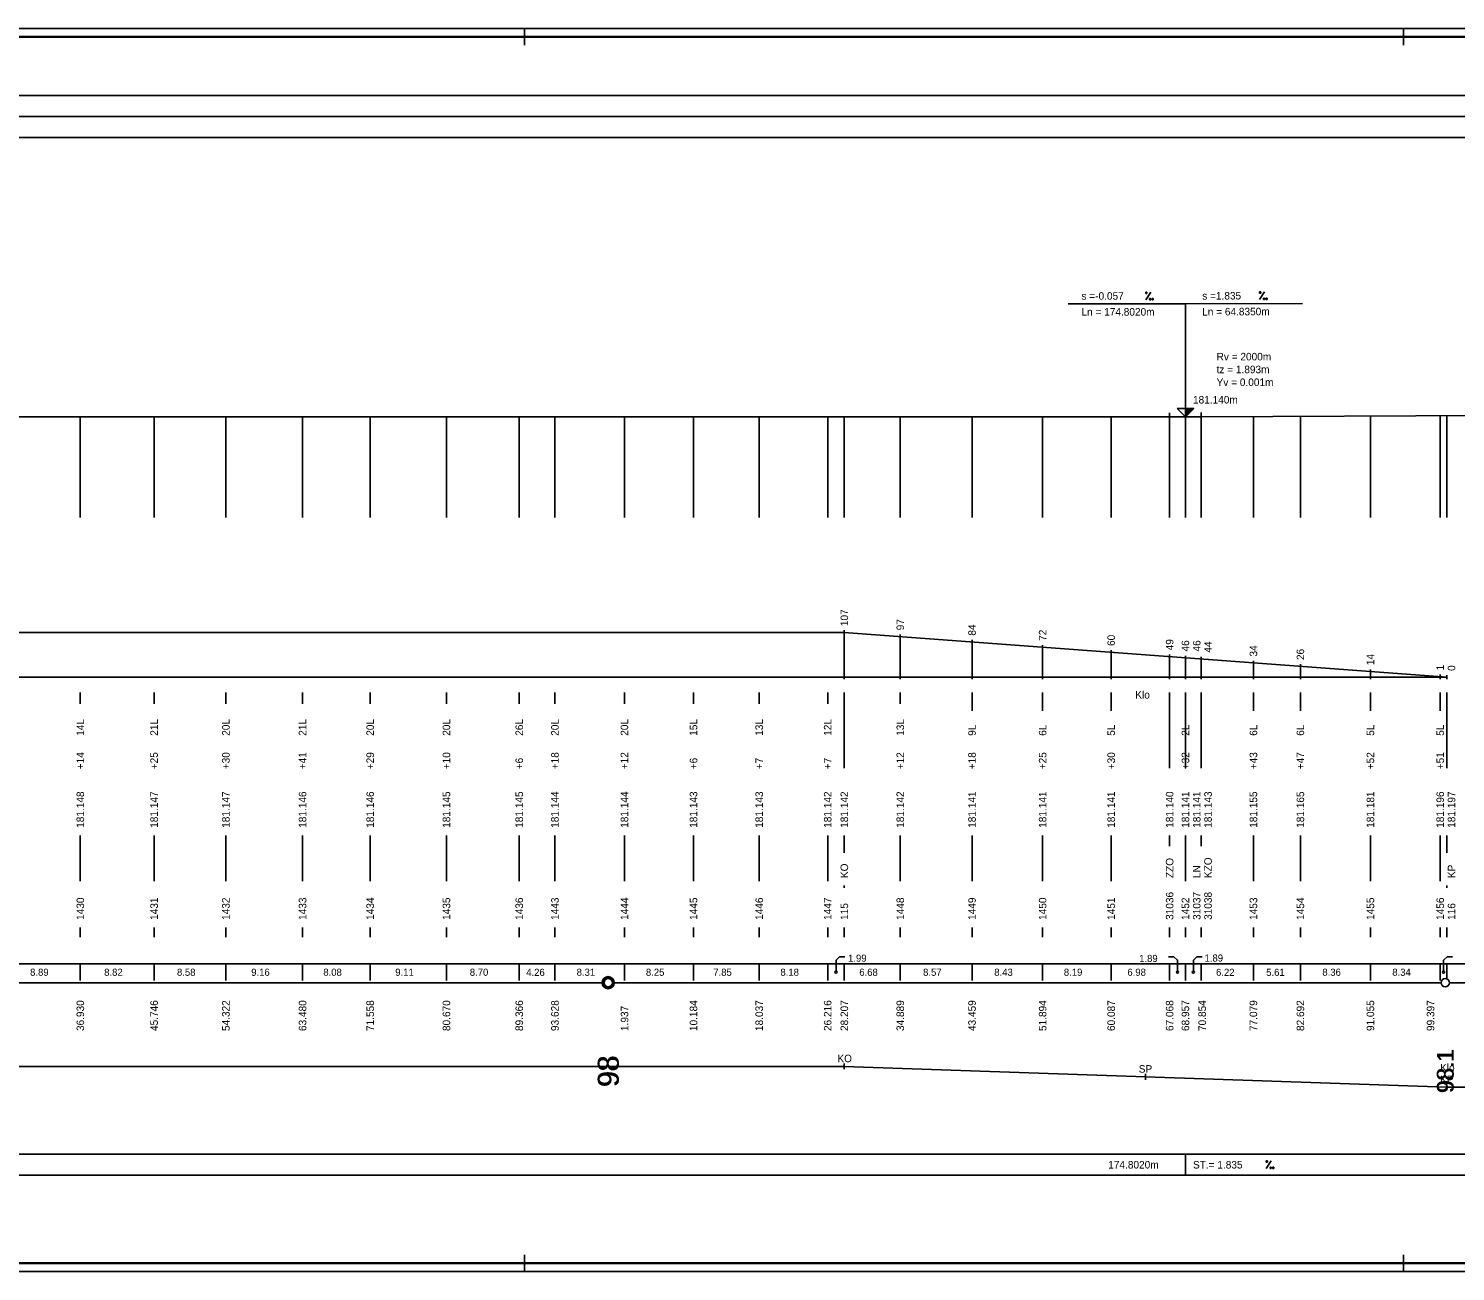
# Model space of a CAD drawing. Extents: x 0 to 10087, y -805 to 297.
# Drawn here: x 3241.5 to 3582.4, y 0 to 297 of the extents above; entities that cross this region are included whole.
import ezdxf

# ---------------------------------------------------------------- set-up
doc = ezdxf.new("R2010")
doc.units = 0
for name, color, linetype in [('CARKY_HODNOT', 7, 'Continuous'), ('KRIV1_CARA', 7, 'Continuous'), ('KRIV1_TEXT', 7, 'Continuous'), ('NIVELETA_CARA', 7, 'Continuous'), ('NIVELETA_TEXT', 7, 'Continuous'), ('PREV_CARA', 7, 'Continuous'), ('PREV_TEXT', 7, 'Continuous'), ('RAM', 7, 'Continuous'), ('REZERVA', 7, 'Continuous'), ('STAN_CARA', 7, 'Continuous'), ('STAN_PAS', 7, 'Continuous'), ('STAN_TEXT', 7, 'Continuous'), ('TEXT', 7, 'Continuous'), ('TXT_C_BODU', 7, 'Continuous')]:
    doc.layers.add(name, color=color, linetype=linetype)

msp = doc.modelspace()

# ---------------------------------------------------------------- linework, layer by layer
at = {"layer": 'CARKY_HODNOT'}
for p, q in [((3253.86, 180.14), (3253.86, 204.24)), ((3271.49, 180.14), (3271.49, 204.24)), ((3288.64, 180.14), (3288.64, 204.23)), ((3306.96, 180.14), (3306.96, 204.23)), ((3323.12, 180.14), (3323.12, 204.23)), ((3341.34, 180.14), (3341.34, 204.23)), ((3358.73, 180.14), (3358.73, 204.22)), ((3367.26, 180.14), (3367.26, 204.22)), ((3383.87, 180.14), (3383.87, 204.22)), ((3400.37, 180.14), (3400.37, 204.22)), ((3416.07, 180.14), (3416.07, 204.21)), ((3432.43, 180.14), (3432.43, 204.21)), ((3436.41, 180.14), (3436.41, 204.21)), ((3449.78, 180.14), (3449.78, 204.21)), ((3466.92, 180.14), (3466.92, 204.21)), ((3483.79, 180.14), (3483.79, 204.2)), ((3500.17, 180.14), (3500.17, 204.2)), ((3514.14, 180.14), (3514.14, 204.2)), ((3517.91, 180.14), (3517.91, 204.2)), ((3517.92, 180.14), (3517.92, 204.2)), ((3521.71, 180.14), (3521.71, 204.22)), ((3534.16, 180.14), (3534.16, 204.27)), ((3545.38, 180.14), (3545.38, 204.33)), ((3562.11, 180.14), (3562.11, 204.4)), ((3578.79, 180.14), (3578.79, 204.48)), ((3580.41, 180.14), (3580.41, 204.49)), ((3253.86, 135.65), (3253.86, 138.35)), ((3271.49, 135.65), (3271.49, 138.35)), ((3288.64, 135.65), (3288.64, 138.35)), ((3306.96, 135.65), (3306.96, 138.35)), ((3323.12, 135.65), (3323.12, 138.35)), ((3341.34, 135.65), (3341.34, 138.35)), ((3358.73, 135.65), (3358.73, 138.35)), ((3367.26, 135.65), (3367.26, 138.35)), ((3383.87, 135.65), (3383.87, 138.35)), ((3400.37, 135.65), (3400.37, 138.35)), ((3416.07, 135.65), (3416.07, 138.35)), ((3432.43, 135.65), (3432.43, 138.35)), ((3436.41, 126.2), (3436.41, 138.35)), ((3449.78, 135.65), (3449.78, 138.35)), ((3466.92, 134), (3466.92, 138.35)), ((3483.79, 134), (3483.79, 138.35)), ((3500.17, 134), (3500.17, 138.35)), ((3514.14, 126.2), (3514.14, 138.35)), ((3517.91, 134), (3517.91, 138.35)), ((3517.92, 126.2), (3517.92, 138.35)), ((3521.71, 126.2), (3521.71, 138.35)), ((3534.16, 134), (3534.16, 138.35)), ((3545.38, 134), (3545.38, 138.35)), ((3562.11, 134), (3562.11, 138.35)), ((3578.79, 134), (3578.79, 138.35)), ((3580.41, 126.2), (3580.41, 138.35)), ((3436.41, 120.25), (3436.41, 126.2)), ((3514.14, 120.25), (3514.14, 126.2)), ((3517.92, 120.25), (3517.92, 126.2)), ((3521.71, 120.25), (3521.71, 126.2)), ((3580.41, 120.25), (3580.41, 126.2)), ((3253.86, 93.3), (3253.86, 104.2)), ((3271.49, 93.3), (3271.49, 104.2)), ((3288.64, 93.3), (3288.64, 104.2)), ((3306.96, 93.3), (3306.96, 104.2)), ((3323.12, 93.3), (3323.12, 104.2)), ((3341.34, 93.3), (3341.34, 104.2)), ((3358.73, 93.3), (3358.73, 104.2)), ((3367.26, 93.3), (3367.26, 104.2)), ((3383.87, 93.3), (3383.87, 104.2)), ((3400.37, 93.3), (3400.37, 104.2)), ((3416.07, 93.3), (3416.07, 104.2)), ((3432.43, 93.3), (3432.43, 104.2)), ((3436.41, 100), (3436.41, 104.2)), ((3449.78, 93.3), (3449.78, 104.2)), ((3466.92, 93.3), (3466.92, 104.2)), ((3483.79, 93.3), (3483.79, 104.2)), ((3500.17, 93.3), (3500.17, 104.2)), ((3514.14, 101.65), (3514.14, 104.2)), ((3517.91, 93.3), (3517.91, 104.2)), ((3517.92, 100), (3517.92, 104.2)), ((3521.71, 101.65), (3521.71, 104.2)), ((3534.16, 93.3), (3534.16, 104.2)), ((3545.38, 93.3), (3545.38, 104.2)), ((3562.11, 93.3), (3562.11, 104.2)), ((3578.79, 93.3), (3578.79, 104.2)), ((3580.41, 100), (3580.41, 104.2)), ((3436.41, 91.65), (3436.41, 92.2)), ((3580.41, 91.65), (3580.41, 92.2)), ((3253.86, 79.9), (3253.86, 82.2)), ((3271.49, 79.9), (3271.49, 82.2)), ((3288.64, 79.9), (3288.64, 82.2)), ((3306.96, 79.9), (3306.96, 82.2)), ((3323.12, 79.9), (3323.12, 82.2)), ((3341.34, 79.9), (3341.34, 82.2)), ((3358.73, 79.9), (3358.73, 82.2)), ((3367.26, 79.9), (3367.26, 82.2)), ((3383.87, 79.9), (3383.87, 82.2)), ((3400.37, 79.9), (3400.37, 82.2)), ((3416.07, 79.9), (3416.07, 82.2)), ((3432.43, 79.9), (3432.43, 82.2)), ((3436.41, 79.9), (3436.41, 82.2)), ((3449.78, 79.9), (3449.78, 82.2)), ((3466.92, 79.9), (3466.92, 82.2)), ((3483.79, 79.9), (3483.79, 82.2)), ((3500.17, 79.9), (3500.17, 82.2)), ((3514.14, 79.9), (3514.14, 82.2)), ((3517.91, 79.9), (3517.91, 82.2)), ((3517.92, 79.9), (3517.92, 82.2)), ((3521.71, 79.9), (3521.71, 82.2)), ((3534.16, 79.9), (3534.16, 82.2)), ((3545.38, 79.9), (3545.38, 82.2)), ((3562.11, 79.9), (3562.11, 82.2)), ((3578.79, 79.9), (3578.79, 82.2)), ((3580.41, 79.9), (3580.41, 82.2))]:
    msp.add_line(p, q, dxfattribs=at)
at = {"layer": 'KRIV1_CARA'}
for p, q in [((3011.07, 49), (3436.41, 49)), ((3436.41, 49), (3436.41, 49.7)), ((3436.41, 49), (3580.41, 44)), ((3436.41, 49), (3436.41, 48.3)), ((3508.41, 46.5), (3508.41, 47.2)), ((3508.41, 46.5), (3508.41, 45.8)), ((3580.41, 44), (3580.41, 44.7)), ((3580.41, 44), (3580.41, 43.3)), ((3580.41, 44), (4035.16, 44))]:
    msp.add_line(p, q, dxfattribs=at)
at = {"layer": 'NIVELETA_CARA'}
for p, q in [((300, 281), (8321.33, 281)), ((300, 276), (8321.33, 276)), ((300, 271), (8321.33, 271)), ((3517.92, 231.2), (3489.92, 231.2)), ((3517.92, 231.2), (3545.92, 231.33)), ((3517.92, 204.2), (3517.92, 231.2)), ((3514.14, 204.2), (3514.14, 205.2)), ((3517.92, 204.2), (3515.92, 206.2)), ((3515.92, 206.2), (3519.92, 206.2)), ((3517.92, 204.2), (3517.92, 206.2)), ((3519.92, 206.2), (3517.92, 204.2)), ((3517.99, 204.27), (3517.99, 206.2)), ((3518.06, 204.33), (3518.06, 206.2)), ((3518.12, 204.4), (3518.12, 206.2)), ((3518.19, 204.47), (3518.19, 206.2)), ((3518.26, 204.53), (3518.26, 206.2)), ((3518.32, 204.6), (3518.32, 206.2)), ((3518.39, 204.67), (3518.39, 206.2)), ((3518.46, 204.73), (3518.46, 206.2)), ((3518.52, 204.8), (3518.52, 206.2)), ((3518.59, 204.87), (3518.59, 206.2)), ((3518.66, 204.93), (3518.66, 206.2)), ((3518.72, 205), (3518.72, 206.2)), ((3518.79, 205.07), (3518.79, 206.2)), ((3518.86, 205.13), (3518.86, 206.2)), ((3518.92, 205.2), (3518.92, 206.2)), ((3518.99, 205.27), (3518.99, 206.2)), ((3519.06, 205.33), (3519.06, 206.2)), ((3519.12, 205.4), (3519.12, 206.2)), ((3519.19, 205.47), (3519.19, 206.2)), ((3519.26, 205.53), (3519.26, 206.2)), ((3519.32, 205.6), (3519.32, 206.2)), ((3519.39, 205.67), (3519.39, 206.2)), ((3519.46, 205.73), (3519.46, 206.2)), ((3519.52, 205.8), (3519.52, 206.2)), ((3519.59, 205.87), (3519.59, 206.2)), ((3519.66, 205.93), (3519.66, 206.2)), ((3519.72, 206), (3519.72, 206.2)), ((3519.79, 206.07), (3519.79, 206.2)), ((3519.86, 206.13), (3519.86, 206.2)), ((3519.92, 206.2), (3519.92, 206.2)), ((3521.71, 204.22), (3521.71, 205.22)), ((3521.71, 204.22), (3637.71, 204.75)), ((3175.58, 204.25), (3514.14, 204.2)), ((3514.14, 204.2), (3517.92, 204.2)), ((3514.14, 204.2), (3514.64, 204.2)), ((3514.64, 204.2), (3515.12, 204.2)), ((3517.92, 204.2), (3521.71, 204.22)), ((3520.72, 204.21), (3521.22, 204.22)), ((3521.22, 204.22), (3521.71, 204.22)), ((500, 28), (8321.33, 28)), ((3517.92, 23), (3517.92, 28)), ((500, 23), (8321.33, 23))]:
    msp.add_line(p, q, dxfattribs=at)
at = {"layer": 'NIVELETA_TEXT'}
for p, q in [((3508.42, 232.21), (3509.61, 234)), ((3508.42, 234), (3508.42, 233.7)), ((3508.43, 234), (3508.42, 233.99)), ((3508.42, 233.7), (3508.72, 233.7)), ((3508.72, 234), (3508.43, 234)), ((3508.72, 233.7), (3508.72, 234)), ((3509.33, 232.5), (3509.33, 232.2)), ((3509.34, 232.5), (3509.33, 232.49)), ((3509.33, 232.2), (3509.63, 232.2)), ((3509.63, 232.5), (3509.34, 232.5)), ((3509.63, 232.2), (3509.63, 232.5)), ((3509.95, 232.5), (3509.95, 232.2)), ((3510.24, 232.5), (3509.95, 232.5)), ((3509.95, 232.5), (3509.95, 232.49)), ((3509.95, 232.2), (3510.24, 232.2)), ((3510.24, 232.2), (3510.24, 232.5)), ((3535.62, 232.29), (3536.81, 234.08)), ((3535.62, 234.08), (3535.62, 233.78)), ((3535.91, 234.08), (3535.62, 234.08)), ((3535.62, 234.08), (3535.62, 234.07)), ((3535.62, 233.78), (3535.91, 233.78)), ((3535.91, 233.78), (3535.91, 234.08)), ((3536.53, 232.58), (3536.53, 232.29)), ((3536.54, 232.58), (3536.53, 232.58)), ((3536.53, 232.29), (3536.83, 232.29)), ((3536.83, 232.59), (3536.54, 232.58)), ((3536.83, 232.29), (3536.83, 232.59)), ((3537.15, 232.59), (3537.15, 232.29)), ((3537.44, 232.59), (3537.15, 232.59)), ((3537.15, 232.59), (3537.15, 232.58)), ((3537.15, 232.29), (3537.44, 232.29)), ((3537.44, 232.29), (3537.44, 232.59)), ((3537.22, 24.6), (3538.41, 26.4)), ((3537.22, 26.4), (3537.22, 26.1)), ((3537.23, 26.4), (3537.22, 26.39)), ((3537.22, 26.1), (3537.52, 26.1)), ((3537.52, 26.4), (3537.23, 26.4)), ((3537.52, 26.1), (3537.52, 26.4)), ((3538.13, 24.9), (3538.13, 24.6)), ((3538.14, 24.9), (3538.13, 24.89)), ((3538.13, 24.6), (3538.43, 24.6)), ((3538.43, 24.9), (3538.14, 24.9)), ((3538.43, 24.6), (3538.43, 24.9)), ((3538.75, 24.9), (3538.75, 24.6)), ((3539.04, 24.9), (3538.75, 24.9)), ((3538.75, 24.9), (3538.75, 24.89)), ((3538.75, 24.6), (3539.04, 24.6)), ((3539.04, 24.6), (3539.04, 24.9))]:
    msp.add_line(p, q, dxfattribs=at)
at = {"layer": 'PREV_CARA'}
for p, q in [((3011.07, 152.7), (3436.41, 152.7)), ((3580.41, 142), (3436.41, 152.7)), ((3011.07, 142), (3436.41, 142)), ((3580.41, 142), (3436.41, 142))]:
    msp.add_line(p, q, dxfattribs=at)
at = {"layer": 'PREV_TEXT'}
for p, q in [((3436.41, 141.5), (3436.41, 153.2)), ((3449.78, 141.5), (3449.78, 152.21)), ((3466.92, 141.5), (3466.92, 150.93)), ((3483.79, 141.5), (3483.79, 149.68)), ((3500.17, 141.5), (3500.17, 148.46)), ((3514.14, 141.5), (3514.14, 147.42)), ((3517.91, 141.5), (3517.91, 147.14)), ((3517.92, 141.5), (3517.92, 147.14)), ((3521.71, 141.5), (3521.71, 146.86)), ((3534.16, 141.5), (3534.16, 145.94)), ((3545.38, 141.5), (3545.38, 145.1)), ((3562.11, 141.5), (3562.11, 143.86)), ((3578.79, 141.5), (3578.79, 142.62)), ((3580.41, 141.5), (3580.41, 142.5))]:
    msp.add_line(p, q, dxfattribs=at)
at = {"layer": 'RAM'}
for p, q in [((8636.33, 297), (0, 297)), ((3360, 293), (3360, 297)), ((3570, 293), (3570, 297)), ((8634.33, 295.1), (2, 295.1)), ((8634.33, 295), (2, 295)), ((8634.33, 294.9), (2, 294.9)), ((3360, 0), (3360, 4)), ((3570, 0), (3570, 4)), ((0, 0), (8636.33, 0)), ((2, 2.1), (8634.33, 2.1)), ((2, 2), (8634.33, 2)), ((2, 1.9), (8634.33, 1.9))]:
    msp.add_line(p, q, dxfattribs=at)
at = {"layer": 'REZERVA'}
for centre, radius in [((3380, 69), 1.45), ((3380, 69), 1.4), ((3380, 69), 1.35), ((3380, 69), 1.3), ((3380, 69), 1.25), ((3380, 69), 1.2), ((3380, 69), 1.15), ((3380, 69), 1.1), ((3380, 69), 1.05), ((3380, 69), 1), ((3580, 69), 1)]:
    msp.add_circle(centre, radius, dxfattribs=at)
at = {"layer": 'STAN_CARA'}
for p, q in [((3181, 69), (3378.5, 69)), ((3381.5, 69), (3579, 69)), ((3581, 69), (3779, 69))]:
    msp.add_line(p, q, dxfattribs=at)
at = {"layer": 'STAN_PAS'}
for p, q in [((3434.42, 74.35), (3435.27, 75.2)), ((3435.27, 75.2), (3436.55, 75.2)), ((3515.18, 75.2), (3513.9, 75.2)), ((3516.03, 74.35), (3515.18, 75.2)), ((3519.81, 74.35), (3520.66, 75.2)), ((3520.66, 75.2), (3521.94, 75.2)), ((3579.6, 74.35), (3580.45, 75.2)), ((3580.45, 75.2), (3581.73, 75.2)), ((300, 73.5), (8321.33, 73.5)), ((3253.86, 69.5), (3253.86, 73.5)), ((3271.49, 69.5), (3271.49, 73.5)), ((3288.64, 69.5), (3288.64, 73.5)), ((3306.96, 69.5), (3306.96, 73.5)), ((3323.12, 69.5), (3323.12, 73.5)), ((3341.34, 69.5), (3341.34, 73.5)), ((3358.73, 69.5), (3358.73, 73.5)), ((3367.26, 69.5), (3367.26, 73.5)), ((3383.87, 69.5), (3383.87, 73.5)), ((3400.37, 69.5), (3400.37, 73.5)), ((3416.07, 69.5), (3416.07, 73.5)), ((3432.43, 69.5), (3432.43, 73.5)), ((3434.42, 71.75), (3434.42, 74.35)), ((3436.41, 69.5), (3436.41, 73.5)), ((3449.78, 69.5), (3449.78, 73.5)), ((3466.92, 69.5), (3466.92, 73.5)), ((3483.79, 69.5), (3483.79, 73.5)), ((3500.17, 69.5), (3500.17, 73.5)), ((3514.14, 69.5), (3514.14, 73.5)), ((3516.03, 71.75), (3516.03, 74.35)), ((3517.91, 69.5), (3517.91, 73.5)), ((3517.92, 69.5), (3517.92, 73.5)), ((3519.81, 71.75), (3519.81, 74.35)), ((3521.71, 69.5), (3521.71, 73.5)), ((3534.16, 69.5), (3534.16, 73.5)), ((3545.38, 69.5), (3545.38, 73.5)), ((3562.11, 69.5), (3562.11, 73.5)), ((3578.79, 69.5), (3578.79, 73.5)), ((3579.6, 71.75), (3579.6, 74.35)), ((3580.41, 69.91), (3580.41, 73.5))]:
    msp.add_line(p, q, dxfattribs=at)
for centre in [(3434.42, 71.5), (3516.03, 71.5), (3519.81, 71.5), (3579.6, 71.5)]:
    msp.add_circle(centre, 0.25, dxfattribs=at)

# ---------------------------------------------------------------- texts
at = {"layer": 'KRIV1_TEXT'}
for s, p in [('KO', (3434.76, 50)), ('SP', (3506.76, 47.5)), ('Klo', (3578.76, 47.8)), ('KP', (3578.76, 45))]:
    msp.add_text(s, height=1.8, dxfattribs=at).set_placement(p)
at = {"layer": 'NIVELETA_TEXT'}
for s, rotation, p in [('s =-0.057', 359.9918, (3493.07, 232.2)), ('s =1.835', 0.2629, (3521.92, 232.22)), ('Ln = 174.8020m', 359.9918, (3493.07, 228.4)), ('Ln = 64.8350m', 0.2629, (3521.92, 228.42))]:
    msp.add_text(s, height=1.8, rotation=rotation, dxfattribs=at).set_placement(p)
for s, p in [('Rv = 2000m', (3525.36, 217.7)), ('tz = 1.893m', (3525.36, 214.64)), ('Yv = 0.001m', (3525.36, 211.58)), ('181.140m', (3519.72, 207.4)), ('174.8020m', (3499.47, 24.6)), ('ST.= 1.835', (3519.72, 24.6))]:
    msp.add_text(s, height=1.8, dxfattribs=at).set_placement(p)
at = {"layer": 'PREV_TEXT'}
for s, p in [('107', (3437.31, 154.2)), ('97', (3450.68, 153.21)), ('84', (3467.82, 151.93)), ('72', (3484.69, 150.68)), ('60', (3501.07, 149.46)), ('49', (3515.04, 148.42)), ('46', (3518.81, 148.14)), ('46', (3521.51, 148.14)), ('44', (3524.21, 147.86)), ('34', (3535.06, 146.94)), ('26', (3546.28, 146.1)), ('14', (3563.01, 144.86)), ('1', (3579.69, 143.62)), ('0', (3582.39, 143.5))]:
    msp.add_text(s, height=1.8, rotation=90, dxfattribs=at).set_placement(p)
msp.add_text('Klo', height=1.8, dxfattribs=at).set_placement((3505.94, 136.9))
at = {"layer": 'STAN_TEXT'}
for s, p in [('1.99', (3437.3, 74.01)), ('1.89', (3506.85, 73.95)), ('1.89', (3522.48, 74.04)), ('8.89', (3241.86, 70.65)), ('8.82', (3259.56, 70.65)), ('8.58', (3276.95, 70.65)), ('9.16', (3294.69, 70.65)), ('8.08', (3311.92, 70.65)), ('9.11', (3329.11, 70.65)), ('8.70', (3346.92, 70.65)), ('4.26', (3360.4, 70.63)), ('8.31', (3372.45, 70.65)), ('8.25', (3389, 70.65)), ('7.85', (3405.1, 70.65)), ('8.18', (3421.14, 70.65)), ('6.68', (3439.98, 70.65)), ('8.57', (3455.23, 70.65)), ('8.43', (3472.24, 70.65)), ('8.19', (3488.86, 70.65)), ('6.98', (3504.04, 70.65)), ('6.22', (3525.23, 70.63)), ('5.61', (3537.21, 70.63)), ('8.36', (3550.63, 70.65)), ('8.34', (3567.34, 70.65))]:
    msp.add_text(s, height=1.7, dxfattribs=at).set_placement(p)
for s, height, p in [('36.930', 1.8, (3254.76, 57.45)), ('45.746', 1.8, (3272.39, 57.45)), ('54.322', 1.8, (3289.54, 57.45)), ('63.480', 1.8, (3307.86, 57.45)), ('71.558', 1.8, (3324.02, 57.45)), ('80.670', 1.8, (3342.24, 57.45)), ('89.366', 1.8, (3359.63, 57.45)), ('93.628', 1.8, (3368.16, 57.45)), ('1.937', 1.8, (3384.8, 57.45)), ('10.184', 1.8, (3401.27, 57.45)), ('18.037', 1.8, (3416.97, 57.45)), ('26.216', 1.8, (3433.33, 57.45)), ('28.207', 1.8, (3437.31, 57.45)), ('34.889', 1.8, (3450.68, 57.45)), ('43.459', 1.8, (3467.82, 57.45)), ('51.894', 1.8, (3484.69, 57.45)), ('60.087', 1.8, (3501.07, 57.45)), ('67.068', 1.8, (3515.04, 57.45)), ('68.957', 1.8, (3518.81, 57.45)), ('70.854', 1.8, (3522.81, 57.45)), ('77.079', 1.8, (3535.06, 57.45)), ('82.692', 1.8, (3546.28, 57.45)), ('91.055', 1.8, (3563.01, 57.45)), ('99.397', 1.8, (3577.38, 57.45)), ('    98', 5, (3382.5, 36.8)), ('    98', 5, (3382.5, 36.7)), ('    98', 5, (3382.5, 36.6)), ('    98.1', 4, (3582, 36.84)), ('    98.1', 4, (3582, 36.74)), ('    98.1', 4, (3582, 36.64))]:
    msp.add_text(s, height=height, rotation=90, dxfattribs=at).set_placement(p)
at = {"layer": 'TEXT'}
for s, p in [('14L', (3254.76, 128)), ('21L', (3272.39, 128)), ('20L', (3289.54, 128)), ('21L', (3307.86, 128)), ('20L', (3324.02, 128)), ('20L', (3342.24, 128)), ('26L', (3359.63, 128)), ('20L', (3368.16, 128)), ('20L', (3384.77, 128)), ('15L', (3401.27, 128)), ('13L', (3416.97, 128)), ('12L', (3433.33, 128)), ('13L', (3450.68, 128)), ('9L', (3467.82, 128)), ('6L', (3484.69, 128)), ('5L', (3501.07, 128)), ('2L', (3518.81, 128)), ('6L', (3535.06, 128)), ('6L', (3546.28, 128)), ('5L', (3563.01, 128)), ('5L', (3579.69, 128)), ('+14', (3254.76, 120)), ('+25', (3272.39, 120)), ('+30', (3289.54, 120)), ('+41', (3307.86, 120)), ('+29', (3324.02, 120)), ('+10', (3342.24, 120)), ('+18', (3368.16, 120)), ('+12', (3384.77, 120)), ('+12', (3450.68, 120)), ('+18', (3467.82, 120)), ('+25', (3484.69, 120)), ('+30', (3501.07, 120)), ('+32', (3518.81, 120)), ('+43', (3535.06, 120)), ('+47', (3546.28, 120)), ('+52', (3563.01, 120)), ('+51', (3579.69, 120)), ('+6', (3359.63, 120)), ('+6', (3401.27, 120)), ('+7', (3416.97, 120)), ('+7', (3433.33, 120)), ('181.148', (3254.76, 106)), ('181.147', (3272.39, 106)), ('181.147', (3289.54, 106)), ('181.146', (3307.86, 106)), ('181.146', (3324.02, 106)), ('181.145', (3342.24, 106)), ('181.145', (3359.63, 106)), ('181.144', (3368.16, 106)), ('181.144', (3384.77, 106)), ('181.143', (3401.27, 106)), ('181.143', (3416.97, 106)), ('181.142', (3433.33, 106)), ('181.142', (3437.31, 106)), ('181.142', (3450.68, 106)), ('181.141', (3467.82, 106)), ('181.141', (3484.69, 106)), ('181.141', (3501.07, 106)), ('181.140', (3515.04, 106)), ('181.141', (3518.81, 106)), ('181.141', (3521.51, 106)), ('181.143', (3524.21, 106)), ('181.155', (3535.06, 106)), ('181.165', (3546.28, 106)), ('181.181', (3563.01, 106)), ('181.196', (3579.69, 106)), ('181.197', (3582.39, 106)), ('KO', (3437.31, 94)), ('ZZO', (3515.04, 94)), ('LN', (3521.51, 94)), ('KZO', (3524.21, 94)), ('KP', (3582.39, 94))]:
    msp.add_text(s, height=1.8, rotation=90, dxfattribs=at).set_placement(p)
at = {"layer": 'TXT_C_BODU'}
for s, p in [('1430', (3254.76, 84)), ('1431', (3272.39, 84)), ('1432', (3289.54, 84)), ('1433', (3307.86, 84)), ('1434', (3324.02, 84)), ('1435', (3342.24, 84)), ('1436', (3359.63, 84)), ('1443', (3368.16, 84)), ('1444', (3384.77, 84)), ('1445', (3401.27, 84)), ('1446', (3416.97, 84)), ('1447', (3433.33, 84)), ('1448', (3450.68, 84)), ('1449', (3467.82, 84)), ('1450', (3484.69, 84)), ('1451', (3501.07, 84)), ('31036', (3515.04, 84)), ('1452', (3518.81, 84)), ('31037', (3521.51, 84)), ('31038', (3524.21, 84)), ('1453', (3535.06, 84)), ('1454', (3546.28, 84)), ('1455', (3563.01, 84)), ('1456', (3579.69, 84)), ('115', (3437.31, 84)), ('116', (3582.39, 84))]:
    msp.add_text(s, height=1.8, rotation=90, dxfattribs=at).set_placement(p)

doc.saveas('drawing.dxf')
